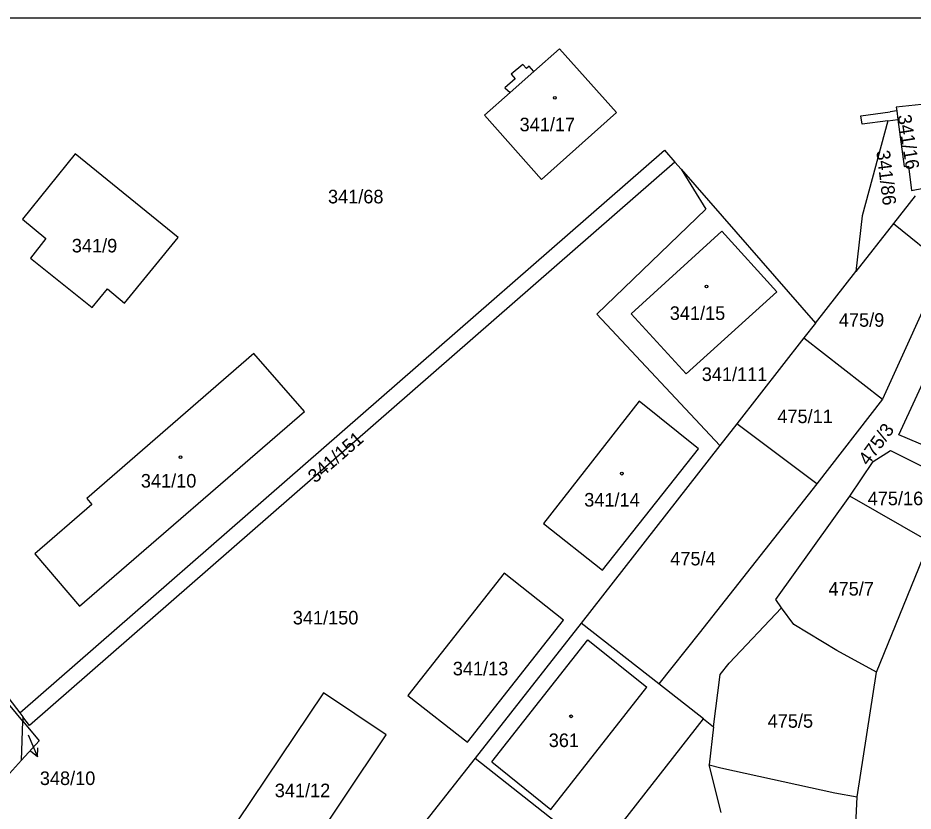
# Model space of a CAD drawing. Extents: x -558358 to -557517, y -1073785 to -1073189.
# Drawn here: x -557909.7 to -557797.5, y -1073289.5 to -1073190.1 of the extents above; entities that cross this region are included whole.
import ezdxf

# ---------------------------------------------------------------- set-up
doc = ezdxf.new("R2010")
doc.units = 0
for name, color, linetype in [('Hranice parcel', 7, 'Continuous'), ('Parcelní čísla', 7, 'Continuous'), ('Pop  PČ popisy', 7, 'Continuous'), ('Vnitřní kresba', 7, 'Continuous'), ('Vrstva 1', 7, 'Continuous'), ('Značky budov', 7, 'Continuous')]:
    doc.layers.add(name, color=color, linetype=linetype)

msp = doc.modelspace()

# ---------------------------------------------------------------- linework, layer by layer
at = {"layer": 'Hranice parcel'}
for p, q in [((-557909.46, -1073277.19), (-557828.67, -1073206.65)), ((-557828.67, -1073206.65), (-557827.35, -1073208.16)), ((-557827.35, -1073208.16), (-557826.56, -1073209.07)), ((-557826.56, -1073209.07), (-557809.74, -1073228.36)), ((-557797.26, -1073212.4), (-557799.96, -1073215.86)), ((-557799.96, -1073215.86), (-557804.68, -1073221.89)), ((-557809.74, -1073228.36), (-557804.68, -1073221.89)), ((-557809.74, -1073228.36), (-557811.18, -1073230.2)), ((-557811.18, -1073230.2), (-557819.59, -1073240.96)), ((-557811.18, -1073230.2), (-557801.34, -1073237.87)), ((-557801.34, -1073237.87), (-557809.56, -1073248.5)), ((-557819.59, -1073240.96), (-557821.71, -1073243.68)), ((-557809.56, -1073248.5), (-557819.59, -1073240.96)), ((-557821.71, -1073243.68), (-557839.11, -1073265.95)), ((-557795.47, -1073255.77), (-557805.42, -1073250.06)), ((-557909.08, -1073278.25), (-557930.32, -1073252.64)), ((-557802.11, -1073272.13), (-557795.8, -1073256.6)), ((-557839.11, -1073265.95), (-557852.38, -1073282.88)), ((-557829.36, -1073273.59), (-557839.11, -1073265.95)), ((-557804.5, -1073287.75), (-557802.11, -1073272.13)), ((-557823.76, -1073277.98), (-557829.36, -1073273.59)), ((-557909.46, -1073277.19), (-557909.06, -1073277.71)), ((-557909.23, -1073283.14), (-557909.08, -1073278.25)), ((-557909.06, -1073277.71), (-557909.08, -1073278.25)), ((-557837.1, -1073294.96), (-557823.76, -1073277.98)), ((-557823.76, -1073277.98), (-557822.5, -1073278.97)), ((-557822.5, -1073278.97), (-557823.08, -1073283.72)), ((-557912.91, -1073287.22), (-557909.23, -1073283.14)), ((-557852.38, -1073282.88), (-557892.99, -1073334.25)), ((-557852.38, -1073282.88), (-557837.1, -1073294.96)), ((-557821.55, -1073289.72), (-557823.08, -1073283.72)), ((-557805.19, -1073300.2), (-557804.5, -1073287.75))]:
    msp.add_line(p, q, dxfattribs=at)
for points in [[(-557845.64, -1073196.14), (-557845.97, -1073196.44), (-557846.43, -1073195.93), (-557847.88, -1073197.13), (-557847.39, -1073197.71), (-557848.66, -1073198.84), (-557848, -1073199.43), (-557851.22, -1073202.29), (-557844.06, -1073210.35), (-557834.66, -1073201.96), (-557841.8, -1073193.95), (-557845.02, -1073196.82), (-557845.64, -1073196.14)], [(-557794.69, -1073211.15), (-557795, -1073208.24), (-557793.89, -1073208.1), (-557794.86, -1073200.76), (-557799.62, -1073201.3), (-557799.56, -1073201.75), (-557800.39, -1073201.86)], [(-557800.69, -1073202.99), (-557803.9, -1073203.42), (-557804.04, -1073202.35), (-557800.39, -1073201.86)], [(-557800.69, -1073202.99), (-557803.91, -1073214.91), (-557804.68, -1073221.89)], [(-557800.69, -1073202.99), (-557799.42, -1073202.82), (-557798.62, -1073208.73), (-557798.08, -1073208.66), (-557797.7, -1073211.74), (-557794.69, -1073211.15)], [(-557906.17, -1073217.76), (-557908.09, -1073220.19), (-557900.4, -1073226.4), (-557898.47, -1073224.04), (-557896.35, -1073225.84), (-557889.61, -1073217.61), (-557902.52, -1073207.11), (-557909.1, -1073215.34), (-557906.17, -1073217.76)], [(-557827.35, -1073208.16), (-557908.24, -1073278.78), (-557909.06, -1073277.71)], [(-557826.56, -1073209.07), (-557823.48, -1073214.05), (-557837.12, -1073227.22), (-557821.71, -1073243.68)], [(-557799.96, -1073215.86), (-557793.64, -1073220.96), (-557801.34, -1073237.87)], [(-557821.48, -1073216.83), (-557832.85, -1073227.17), (-557825.95, -1073234.71), (-557814.6, -1073224.41), (-557821.48, -1073216.83)], [(-557791.11, -1073245.75), (-557793.29, -1073244.89), (-557799.3, -1073242.34), (-557790.59, -1073223.57), (-557786.97, -1073223.95)], [(-557900.41, -1073251.11), (-557907.58, -1073257.29), (-557901.97, -1073263.84), (-557873.78, -1073239.42), (-557880.11, -1073232.15), (-557901.06, -1073250.32), (-557900.41, -1073251.11)], [(-557824.39, -1073244.13), (-557831.84, -1073238.15), (-557843.81, -1073253.48), (-557836.43, -1073259.33), (-557824.39, -1073244.13)], [(-557805.42, -1073250.06), (-557802.52, -1073245.72), (-557800.36, -1073244.34), (-557792.5, -1073248.24)], [(-557809.56, -1073248.5), (-557824.33, -1073267.21), (-557829.36, -1073273.59)], [(-557814, -1073264.03), (-557814.7, -1073263), (-557805.42, -1073250.06)], [(-557930.24, -1073250.53), (-557916.49, -1073268.06), (-557909.46, -1073277.19)], [(-557841.31, -1073265.58), (-557848.76, -1073259.71), (-557860.82, -1073275.02), (-557853.36, -1073280.89), (-557841.31, -1073265.58)], [(-557822.5, -1073278.97), (-557821.7, -1073272.42), (-557820.57, -1073271), (-557814, -1073264.03)], [(-557802.11, -1073272.13), (-557807.06, -1073269.39), (-557812.44, -1073266.12), (-557814, -1073264.03)], [(-557863.55, -1073279.98), (-557871.4, -1073274.72), (-557882.24, -1073290.87), (-557874.41, -1073296.22), (-557863.55, -1073279.98)], [(-557909.08, -1073278.25), (-557907.04, -1073280.71), (-557909.23, -1073283.14)], [(-557823.08, -1073283.72), (-557821.62, -1073284.11), (-557807.33, -1073287.22), (-557804.5, -1073287.75)]]:
    msp.add_lwpolyline(points, dxfattribs=at)
at = {"layer": 'Pop  PČ popisy'}
for p, q in [((-557908.42, -1073279.97), (-557907.25, -1073282.73)), ((-557907.25, -1073282.73), (-557907.18, -1073281.61)), ((-557907.25, -1073282.73), (-557908.1, -1073282.01))]:
    msp.add_line(p, q, dxfattribs=at)
at = {"layer": 'Vnitřní kresba'}
for p, q in [((-557848, -1073199.43), (-557845.02, -1073196.82)), ((-557799.56, -1073201.75), (-557799.42, -1073202.82)), ((-557850.28, -1073283.35), (-557838.25, -1073268.06)), ((-557838.25, -1073268.06), (-557830.86, -1073274.01)), ((-557842.92, -1073289.34), (-557830.86, -1073274.01)), ((-557850.28, -1073283.35), (-557842.92, -1073289.34))]:
    msp.add_line(p, q, dxfattribs=at)
at = {"layer": 'Vrstva 1'}
msp.add_line((-558357.53, -1073190.09), (-557516.53, -1073190.09), dxfattribs=at)
at = {"layer": 'Značky budov'}
for centre in [(-557842.41, -1073200.11), (-557823.39, -1073223.75), (-557889.3, -1073245.15), (-557834.01, -1073247.22), (-557840.37, -1073277.65)]:
    msp.add_circle(centre, 0.175, dxfattribs=at)

# ---------------------------------------------------------------- texts
at = {"layer": 'Parcelní čísla'}
for s, p in [('341/17', (-557846.82, -1073204.3)), ('341/68', (-557870.83, -1073213.34)), ('341/9', (-557902.93, -1073219.49)), ('341/15', (-557828, -1073227.95)), ('475/9', (-557806.81, -1073228.81)), ('341/111', (-557823.99, -1073235.61)), ('475/11', (-557814.52, -1073240.89)), ('341/10', (-557894.28, -1073248.97)), ('341/14', (-557838.72, -1073251.35)), ('475/16', (-557803.2, -1073251.18)), ('475/4', (-557827.94, -1073258.73)), ('475/7', (-557808.11, -1073262.51)), ('341/150', (-557875.24, -1073266.13)), ('341/13', (-557855.19, -1073272.51)), ('475/5', (-557815.73, -1073279.08)), ('361', (-557843.17, -1073281.5)), ('348/10', (-557906.94, -1073286.26)), ('341/12', (-557877.5, -1073287.79))]:
    msp.add_text(s, height=1.7, dxfattribs=at).set_placement(p)
for s, rotation, p in [('341/16', 279, (-557799.46, -1073202.33)), ('341/86', 277, (-557802.12, -1073206.77)), ('475/3', 54, (-557803.13, -1073246.32)), ('341/151', 41, (-557872.43, -1073248.49))]:
    msp.add_text(s, height=1.7, rotation=rotation, dxfattribs=at).set_placement(p)

doc.saveas('drawing.dxf')
